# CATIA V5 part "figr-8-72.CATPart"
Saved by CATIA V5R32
Part number: Part1
Bounding box of the stored display mesh (mm): x -81.893 to 81.893, y -175.508 to 175.508, z -50 to 146
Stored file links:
  D:\PROJECTS\Project 2022\CATIA V5 6R 2022\Resources\Part Files\c08_catia_v5_6r2022_prt\figr-8-72.CATPart
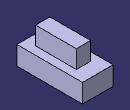
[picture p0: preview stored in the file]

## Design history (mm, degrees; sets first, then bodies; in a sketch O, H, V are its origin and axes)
Body1 (main body)
  Sketch1 on xy-plane, origin (0, 0, 0), H (1, 0, 0), V (0, 1, 0)
    line L1 (-81.8929, 175.5076) -> (81.8929, 175.5076)
    line L2 (81.8929, 175.5076) -> (81.8929, -175.5076)
    line L3 (81.8929, -175.5076) -> (-81.8929, -175.5076)
    line L4 (-81.8929, -175.5076) -> (-81.8929, 175.5076)
    axis line L5 (81.8929, -175.5076) -> (-81.8929, 175.5076)
    horizontal: L1 H, L3 H
    vertical: L2 V, L4 V
    midpoint: O L5
  Pad1: profile Sketch1, direction (0, 0, 1), length 50, mirrored extent
  Body2
    Sketch2 on xy-plane, origin (0, 0, 0), H (1, 0, 0), V (0, 1, 0)
      line L1 (-37.4906, 99.3013) -> (38.4681, 99.3013)
      line L2 (38.4681, 99.3013) -> (38.4681, -118.5305)
      line L3 (38.4681, -118.5305) -> (-37.4906, -118.5305)
      line L4 (-37.4906, -118.5305) -> (-37.4906, 99.3013)
      horizontal: L1 H, L3 H
      vertical: L2 V, L4 V
    Pad2: profile Sketch2, direction (0, 0, 1), length 146, opposite side length 150
  Trim1: tool Body2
